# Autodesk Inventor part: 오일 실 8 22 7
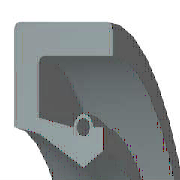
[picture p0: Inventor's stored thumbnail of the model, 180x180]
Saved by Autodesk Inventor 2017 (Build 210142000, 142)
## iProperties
IsCustomPart: 1
Created: 2012-02
Part Number: 오일 실 8 22 7
Material: 고무
Description: 오일-실
Document SubType Name: Modeling
Standard: KS B 2804
Designer: test
Standards Organization: KS
Language: ko-KR
Size Designation: S - 8 22 7
Categories: <MemberInstance><Categories><Category DisplayName="샤프트 부품" InternalName="7f7aeb1f-a693-4053-b835-cee3144e0d98" Mnemonic="SHFT"><Category DisplayName="실링" Intern
Density: 0.93 g/cm^3
Appearance: 고무 - 검은색 - 버전 1.1
Mass: 1.07912 g
Surface Area: 17.6852 cm^2
Volume: 1.16034 cm^3
Author: test
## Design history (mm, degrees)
revolve "본체" stored, may be unused: angle "d17" = 90 deg
revolve "스프링1" stored, may be unused: angle "d18" = 90 deg
body "Solid1"
sketch "스케치1"
  geometry: L1 (0, 11)-(7, 11); L2 (7, 11)-(7, 9.75); L3 (7, 9.75)-(1.75, 9.75); L4 (0, 11)-(0, 6.1); L5 (0, 6.1)-(1.75, 5.75); L6 (1.75, 5.75)-(4.9, 4); L7 (4.9, 4)-(0, 4); L8 (6.3, 4.875)-(6.3, 6.1); L9 (0, 0)-(9.586, 0) reference; L10 (4.9, 4)-(6.3, 4.875); L11 (0, 18)-(0, -3) reference; L12 (-1.917, 0)-(11.503, 0) reference; L13 (4.2, 6.1)-(1.75, 6.59); L14 (1.75, 6.59)-(1.75, 9.75); L15 (6.3, 6.1)-(5.6, 6.1); C1 r 0.455 at (4.9, 6.1); A1 r 0.7 centre (4.9, 6.1) between (5.6, 6.1) and (4.2, 6.1)
  constraints: 26 end point, 5 horizontal alignment, 4 perpendicular, 2 centre point, 2 collinear, 2 horizontal, 2 parallel, 2 point on circle, 2 point on line, 2 vertical alignment, 1 coincident
  dimensions: "d0" = 22 diameter of L1 L9 (= SD2); "d1" = 9.75 diameter of L8.start L9 (= ABDM); "d2" = 1.25 distance of L1.end L2.end (computed from SD); "d3" = 0.91 diameter of C1 (= SPDI); "d4" = 1.4 diameter of A1 (= SPDA); "d5" = 8 diameter of L6.end L9 (= NND); "d6" = 11.5 diameter of L5.end L9 (= TKDM); "d7" = 12.2 diameter of L4.end L9 (= HLDM); "d8" = 4.9 distance from line of C1.centre L4 (= SPDST); "d9" = 6.3 distance between parallel lines of L8 L4 (= SDI); "d10" = 7 distance between parallel lines of L2 L4 (= SWDT); "d12" = 1.75 distance between parallel lines of L14 L4 (= SD)
fillet "모깎기1" dims "d11" = 0.3 (= RR)
other parameters: "SD2" = 22 [user parameter; used in 1 equation term], "SWDT" = 7 [user parameter; used in 1 equation term], "RR" = 0.3 [user parameter; used in 1 equation term], "SD" = 1.75 [user parameter; used in 2 equation terms], "NND" = 8 [user parameter; used in 1 equation term], "SPDA" = 1.4 [user parameter; used in 1 equation term], "SPDI" = 0.91 [user parameter; used in 1 equation term], "TKDM" = 11.5 [user parameter; used in 1 equation term], "HLDM" = 12.2 [user parameter; used in 1 equation term], "ABDM" = 9.75 [user parameter; used in 1 equation term], "SDI" = 6.3 [user parameter; used in 1 equation term], "SPDST" = 4.9 [user parameter; used in 1 equation term], "d13" = 0, "d14" = 0, "d15" = 0, "LAB" = 0.35 [user parameter]
